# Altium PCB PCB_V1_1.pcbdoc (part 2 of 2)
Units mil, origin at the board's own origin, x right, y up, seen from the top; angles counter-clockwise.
Board outline 2047.24 x 3937.01 mil, 2 copper layers (Top Layer, Bottom Layer), stack 62.206 mil thick; 99 components, 62 nets, 329 pads, 46 vias.
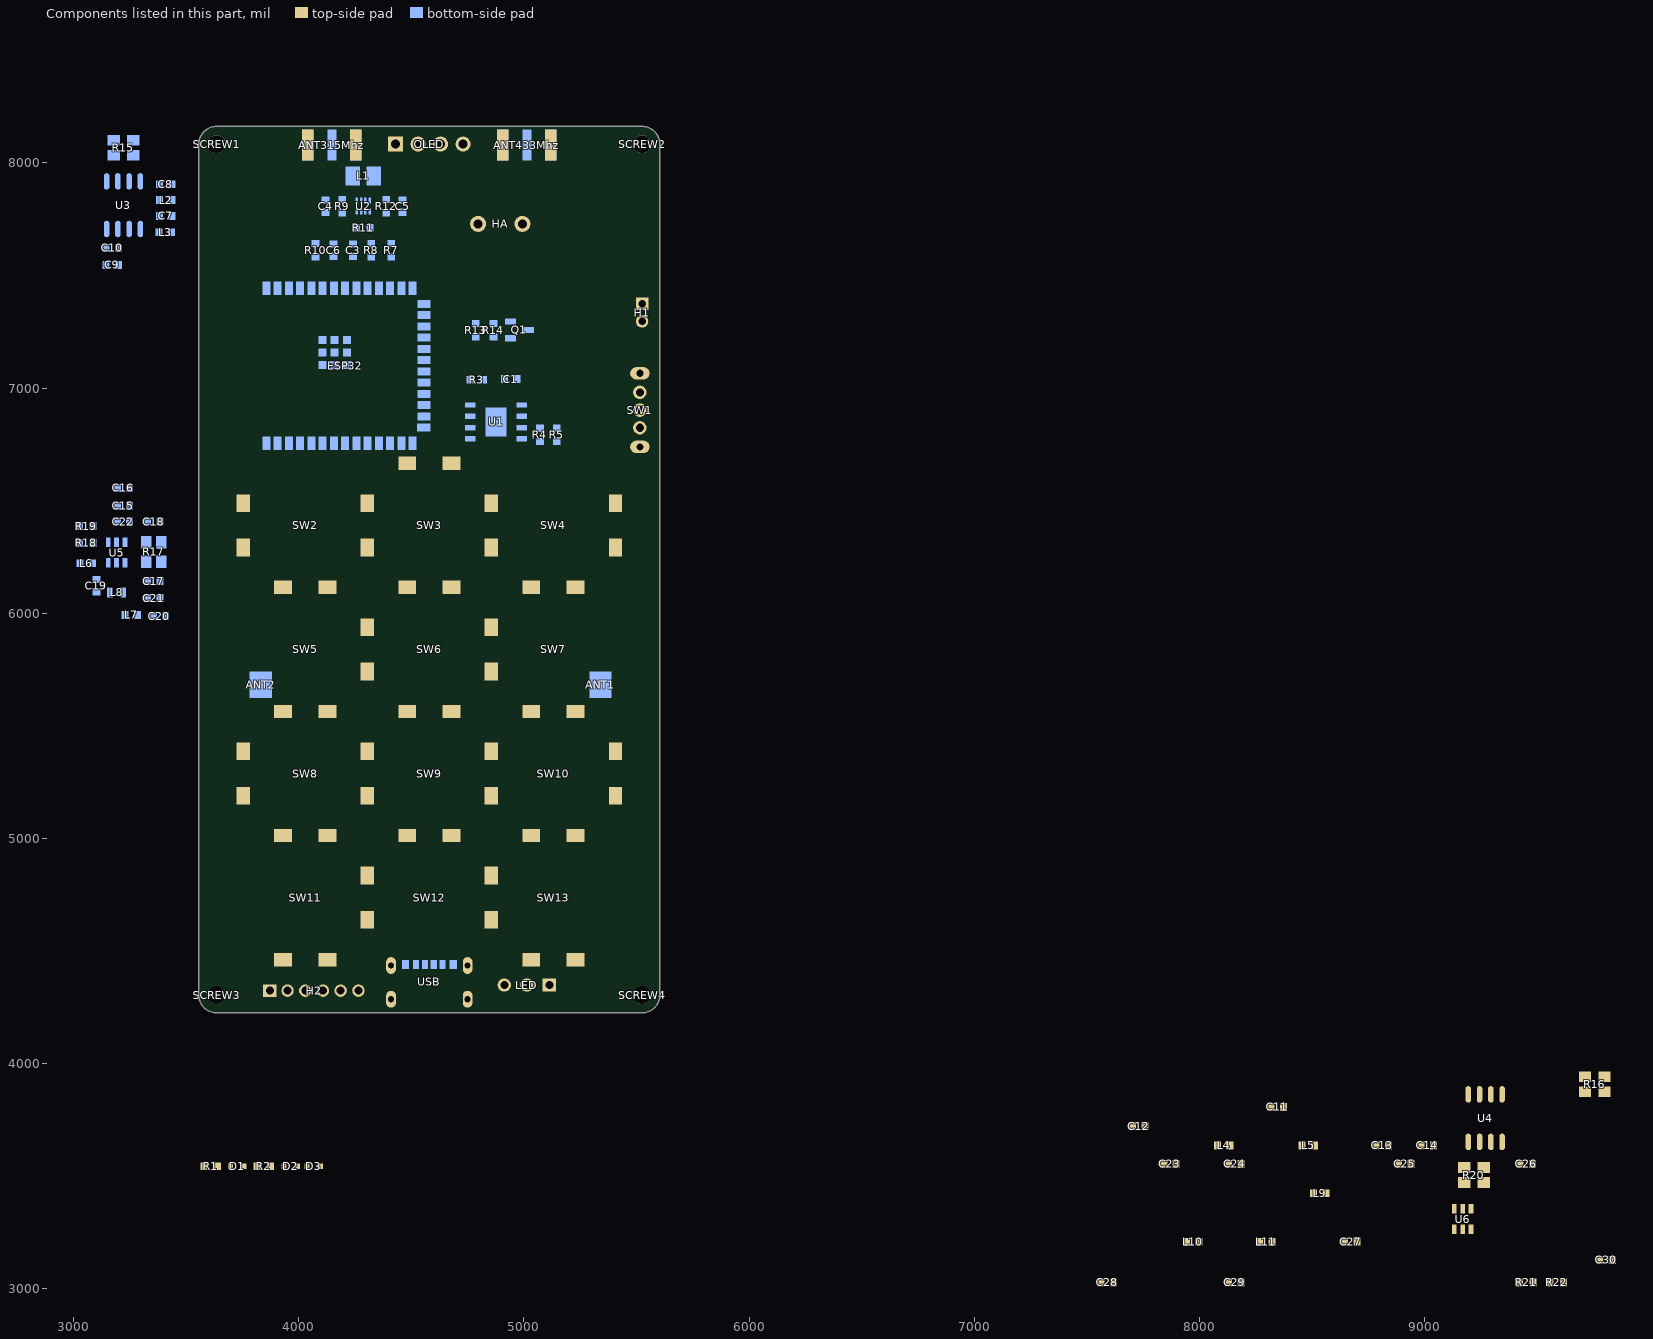
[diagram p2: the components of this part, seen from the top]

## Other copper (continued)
Bottom Layer:
  region net 433ANT: 5046.21,7999 5036.02,7971.29 ccw(c4966.71,7939.25) 4993.07,8010.91 5032.44,8010.91 ccw(c5055.12,8023.21)
  region net 315ANT: 4160.83,7987.48 4131.3,7987.48 ccw(c4066.33,7987.48) 4126.93,8010.91 4166.3,8010.91 ccw(c4213.7,7987.48)
  region net B+: 5475.25,6989.16 5478.71,7013.98 5479.83,7012.97 5481.09,7012.06 5483.96,7010.5 5487.16,7009.31 5490.59,7008.51 5494.09,7008.11 5497.55,7008.11 5500.83,7008.53 5503.81,7009.38 5487.94,6967.57 5484.97,6973.81 5482.56,6979.07 5481.23,6981.53 5479.66,6983.98 5477.71,6986.49
  region net VCC: 5478.51,6924.56 5492.65,6938.7 5495.17,6936.58 5497.8,6935.05 5500.55,6934.02 5503.43,6933.38 5506.44,6933.02 5509.57,6932.84 5516.24,6932.59 5484.62,6900.97 5484.37,6907.64 5484.19,6910.77 5483.83,6913.78 5483.19,6916.65 5482.16,6919.41 5480.63,6922.04
  region net VBUS: 4648.74,4410.85 4628.74,4410.85 ccw(c4613.62,4410.85) 4624.96,4420.85 4652.52,4420.85 ccw(c4663.86,4410.85)
  region net VBUS: 4628.74,4464.8 4648.74,4464.8 ccw(c4653.42,4464.8) 4652.52,4460.22 4624.96,4460.22 ccw(c4624.07,4464.8)
  region net VBUS: 4631.07,4477.48 4651.07,4477.48 ccw(c4754.09,4477.48) 4652.52,4460.22 4624.96,4460.22 ccw(c4603.6,4477.48)
  region net VBUS: 4510.63,4470.22 4530.63,4470.22 ccw(c4545.75,4470.22) 4534.41,4460.22 4506.85,4460.22 ccw(c4495.52,4470.22)
  region net TXD: 4152.28,4343.46 4166.43,4357.6 4168.61,4355.75 4170.97,4354.34 4173.48,4353.3 4176.11,4352.58 4178.85,4352.09 4181.68,4351.78 4187.52,4351.41 4158.47,4322.36 4158.11,4328.2 4157.79,4331.03 4157.31,4333.78 4156.58,4336.41 4155.55,4338.92 4154.14,4341.27
  region net BOOT: 3983.47,4304.34 3969.33,4290.19 3967.14,4292.05 3964.78,4293.46 3962.28,4294.49 3959.65,4295.22 3956.9,4295.71 3954.07,4296.02 3948.23,4296.38 3977.28,4325.43 3977.65,4319.59 3977.96,4316.76 3978.45,4314.02 3979.17,4311.39 3980.21,4308.88 3981.62,4306.52
  region net $1N804: 4717.1,6834.58 4732.79,6847.18 ccw(c4764.61,6889.61) 4764.61,6836.57 4737.9,6812.95 ccw(c4178.52,6296)
  region net VBUS: 4796.07,6932.48 4796.07,6912.48 ccw(c4785.14,6786.03) 4785.14,6912.95 4785.14,6936.57 ccw(c4796.07,6949.1)
  region net B+: 5021.07,6937.48 5021.07,6917.48 ccw(c5021.07,6909.92) 5014.14,6912.95 5014.14,6936.57 ccw(c5014.14,6963.45)
  region net $1N7064: 5044.14,6884.76 5044.14,6864.76 ccw(c5044.14,6615.37) 5014.14,6862.95 5014.14,6886.57 ccw(c5044.14,7134.15)
  region net $1N6847: 5044.14,6834.76 5044.14,6814.76 ccw(c5044.14,6565.37) 5014.14,6812.95 5014.14,6836.57 ccw(c5044.14,7084.15)
  region net VBUS: 4962.87,6764.76 4962.87,6784.76 ccw(c4962.87,6790.16) 4966.9,6786.57 4966.9,6762.95 ccw(c4962.87,6759.37)
  region net VBUS: 5001.07,6732.95 4981.07,6732.95 ccw(c4942.22,6732.95) 4966.9,6762.95 5014.14,6762.95 ccw(c5042.02,6732.95)
  region net +3.3V: 3895.48,7503.51 3915.48,7503.51 ccw(c3977.65,7503.51) 3923.19,7473.51 3887.76,7473.51 ccw(c3833.3,7503.51)
  region net EN: 3945.48,7476.89 3965.48,7476.89 ccw(c3973.19,7483.99) 3973.19,7473.51 3937.76,7473.51 ccw(c3937.76,7483.99)
  region net ADC: 3995.64,7486.89 4015.32,7486.89 ccw(c4030.64,7486.89) 4023.19,7473.51 3987.76,7473.51 ccw(c3980.32,7486.89)
  region net 315_TX: 4215.48,7404.45 4195.48,7404.45 ccw(c4185.14,7404.45) 4187.76,7414.45 4223.19,7414.45 ccw(c4225.82,7404.45)
  region net 433_TX: 4245.48,7482.48 4265.48,7482.48 ccw(c4274.56,7482.48) 4273.19,7473.51 4237.76,7473.51 ccw(c4236.4,7482.48)
  region net I2C_SDA: 4615.4,7384.49 4615.4,7364.49 ccw(c4615.4,7302.31) 4585.4,7356.77 4585.4,7392.2 ccw(c4615.4,7446.66)
  region net BUZZER: 4615.4,7334.49 4615.4,7314.49 ccw(c4615.4,7252.31) 4585.4,7306.77 4585.4,7342.2 ccw(c4615.4,7396.66)
  region net 433_RX: 4615.4,7134.49 4615.4,7114.49 ccw(c4615.4,7052.31) 4585.4,7106.77 4585.4,7142.2 ccw(c4615.4,7196.66)
  region net KEY_ENTER: 4615.4,7084.49 4615.4,7064.49 ccw(c4615.4,7002.31) 4585.4,7056.77 4585.4,7092.2 ccw(c4615.4,7146.66)
  region net KEY_3: 4614.06,7034.49 4614.06,7014.49 ccw(c4614.06,6957.39) 4585.4,7006.77 4585.4,7042.2 ccw(c4614.06,7091.58)
  region net KEY_6: 4604.06,6984.49 4604.06,6964.49 ccw(c4604.06,6938.06) 4585.4,6956.77 4585.4,6992.2 ccw(c4604.06,7010.92)
  region net KEY_9: 4591.07,6934.49 4591.07,6914.49 ccw(c4593.48,6906.77) 4585.4,6906.77 4585.4,6942.2 ccw(c4593.48,6942.2)
  region net KEY_MENU: 4508.14,6840.41 4507.78,6868.34 ccw(c4421.68,6954.43) 4526.34,6892.2 4526.34,6856.77 ccw(c4670.91,6677.64)
  region net KEY_2: 4564.69,6776.77 4544.69,6776.77 ccw(c4507.19,6776.77) 4529.69,6806.77 4579.69,6806.77 ccw(c4602.19,6776.77)
  region net BOOT: 4515.48,6695.47 4495.48,6695.47 ccw(c4433.3,6695.47) 4487.76,6725.47 4523.19,6725.47 ccw(c4577.65,6695.47)
  region net KEY_5: 4465.48,6695.47 4445.48,6695.47 ccw(c4383.3,6695.47) 4437.76,6725.47 4473.19,6725.47 ccw(c4527.65,6695.47)
  region net KEY_8: 4416.07,6695.47 4396.07,6695.47 ccw(c4337.73,6695.47) 4387.76,6725.47 4423.19,6725.47 ccw(c4482.76,6695.47)
  region net KEY_BACK: 4366.07,6695.47 4346.07,6695.47 ccw(c4287.73,6695.47) 4337.76,6725.47 4373.19,6725.47 ccw(c4432.76,6695.47)
  region net KEY_1: 4315.48,6695.47 4295.48,6695.47 ccw(c4233.3,6695.47) 4287.76,6725.47 4323.19,6725.47 ccw(c4377.65,6695.47)
  region net KEY_4: 4265.48,6695.47 4245.48,6695.47 ccw(c4183.3,6695.47) 4237.76,6725.47 4273.19,6725.47 ccw(c4327.65,6695.47)
  region net KEY_7: 4215.48,6695.47 4195.48,6695.47 ccw(c4133.3,6695.47) 4187.76,6725.47 4223.19,6725.47 ccw(c4277.65,6695.47)
  region net 315_RX: 4115.48,6695.47 4095.48,6695.47 ccw(c4033.3,6695.47) 4087.76,6725.47 4123.19,6725.47 ccw(c4177.65,6695.47)
  region net RXD: 4065.48,6695.47 4045.48,6695.47 ccw(c3983.3,6695.47) 4037.76,6725.47 4073.19,6725.47 ccw(c4127.65,6695.47)
  region net TXD: 4015.48,6695.47 3995.48,6695.47 ccw(c3933.3,6695.47) 3987.76,6725.47 4023.19,6725.47 ccw(c4077.65,6695.47)
  region net I2C_SCL: 3945.48,6792.48 3965.48,6792.48 ccw(c3973.44,6792.48) 3973.19,6784.53 3937.76,6784.53 ccw(c3937.52,6792.48)
  region net $1N6847: 5024.06,6814.76 5024.06,6834.76 ccw(c5024.06,6974.7) 5054.06,6838.02 5054.06,6806.27 ccw(c5024.06,6757.56)
  region net $1N11631: 5081.07,6716.95 5061.07,6716.95 ccw(c4993.35,6716.95) 5054.06,6746.95 5088.07,6746.95 ccw(c5148.78,6716.95)
  region net $1N7064: 5136.07,6852.48 5156.07,6852.48 ccw(c5174.5,6852.48) 5163.07,6838.02 5129.06,6838.02 ccw(c5117.64,6852.48)
  region net $1N7056: 5156.07,6716.95 5136.07,6716.95 ccw(c5068.35,6716.95) 5129.06,6746.95 5163.07,6746.95 ccw(c5223.78,6716.95)
  region net $1N804: 4741.07,7027.48 4741.07,7047.48 ccw(c4737.8,7054.49) 4745.53,7054.49 4745.53,7020.47 ccw(c4737.8,7020.47)
  region net +3.3V: 4568.39,8054.3 4550.62,8043.79 4549.09,8045.2 4547.6,8046.37 4546.12,8047.33 4544.66,8048.08 4541.73,8049.11 4538.73,8049.64 4535.57,8049.87 4532.19,8049.99 4528.48,8050.2 4524.39,8050.69 4563.11,8082.15 4562.65,8074.32 4562.55,8070.61 4562.7,8067.04 4563.24,8063.62 4563.69,8061.96 4564.28,8060.35 4565.03,8058.77 4565.96,8057.24 4567.07,8055.75
  region net $1N7056: 5138.75,4389.03 5152.89,4374.89 ccw(c5195.32,4343.07) 5142.29,4343.07 5106.93,4378.43 ccw(c5106.93,4431.46)
  region net VBUS: 5022.76,4314.17 5002.76,4314.17 5002.69,4315.75 5002.49,4317.13 5002.17,4318.33 5001.73,4319.38 5000.54,4321.12 4999.01,4322.55 4995.16,4325.3 4992.99,4327.01 4990.75,4329.21 5034.77,4329.21 5032.53,4327.01 5030.36,4325.3 5026.51,4322.55 5024.98,4321.12 5023.79,4319.38 5023.35,4318.33 5023.03,4317.13 5022.83,4315.75
  region net $1N11631: 4934.22,4384.5 4948.37,4370.36 4946.29,4367.91 4944.79,4365.33 4943.76,4362.62 4943.1,4359.79 4942.72,4356.84 4942.51,4353.76 4942.24,4347.25 4911.12,4378.38 4917.63,4378.65 4920.7,4378.86 4923.65,4379.24 4926.48,4379.9 4929.19,4380.93 4931.77,4382.43
  region net $1N15783: 4886.03,7211.46 4886.03,7231.46 ccw(c4886.03,7352.41) 4916.03,7235.24 4916.03,7207.68 ccw(c4886.03,7090.51)
  region net $1N15750: 5009.38,7302.64 5029.38,7302.64 ccw(c5067.49,7302.64) 5043.98,7272.64 4994.77,7272.64 ccw(c4971.26,7302.64)
  region net +3.3V: 5041.5,7739.41 5041.5,7719.41 5039.29,7719.32 5037.28,7719.04 5035.43,7718.6 5033.72,7718 5032.14,7717.26 5030.66,7716.38 5027.92,7714.28 5025.33,7711.8 5022.71,7709.03 5019.89,7706.06 5016.7,7703 5016.7,7755.82 5019.89,7752.76 5022.71,7749.79 5025.33,7747.02 5027.92,7744.54 5030.66,7742.44 5032.14,7741.56 5033.72,7740.82 5035.43,7740.22 5037.28,7739.78 5039.29,7739.5
  region net +3.3V: 4951.76,7756.58 4965.9,7770.72 4967.53,7769.23 4969.15,7768 4970.77,7767 4972.4,7766.22 4974.04,7765.63 4975.71,7765.2 4979.13,7764.75 4982.72,7764.67 4986.53,7764.78 4990.62,7764.88 4995.05,7764.79 4957.7,7727.44 4957.6,7731.86 4957.7,7735.95 4957.81,7739.76 4957.74,7743.35 4957.28,7746.78 4956.86,7748.44 4956.26,7750.08 4955.48,7751.71 4954.49,7753.33 4953.26,7754.95
  region net B+: 5505.01,7262.64 5490.87,7276.78 5492.72,7278.97 5494.13,7281.32 5495.17,7283.83 5495.89,7286.46 5496.38,7289.2 5496.69,7292.03 5497.05,7297.87 5526.1,7268.82 5520.26,7268.46 5517.43,7268.15 5514.69,7267.66 5512.06,7266.93 5509.55,7265.9 5507.2,7264.49
  region net B+: 5486.91,7286.5 5486.91,7306.18 5489.79,7306.42 5492.47,7307.1 5494.96,7308.16 5497.32,7309.52 5499.58,7311.14 5501.79,7312.95 5506.2,7316.88 5506.2,7275.8 5501.79,7279.73 5499.58,7281.53 5497.32,7283.15 5494.96,7284.52 5492.47,7285.58 5489.79,7286.26
  region net 433ANT: 5427.9,5696.93 5427.9,5667.4 ccw(c5427.9,5621.72) 5388.74,5645.26 5388.74,5719.08 ccw(c5427.9,5742.61)
  region net 315ANT: 3739.63,5685.66 3739.63,5718.04 ccw(c3756.05,5751.7) 3781.85,5724.56 3781.85,5650.75 ccw(c3703.65,5599.15)
  region net B+: 5015.23,7049.76 5015.23,7029.76 ccw(c5015.23,6967.59) 4985.23,7022.05 4985.23,7057.48 ccw(c5015.23,7111.94)
  region net ADC: 4250.91,7547.48 4231.22,7547.48 ccw(c4197.41,7547.48) 4223.35,7569.17 4258.78,7569.17 ccw(c4284.73,7547.48)
  region net ADC: 4288.31,7592.66 4288.31,7572.98 ccw(c4288.31,7456.52) 4258.78,7569.17 4258.78,7600.67 ccw(c4288.31,7651.12)
  region net EN: 4106.68,7570.54 4106.68,7590.54 ccw(c4106.68,7640.05) 4136.68,7600.67 4136.68,7569.17 ccw(c4106.68,7241.39)
  region net VCC: 4458.07,7652.14 4458.07,7632.14 ccw(c4458.07,7552.61) 4428.07,7626.27 4428.07,7658.02 ccw(c4458.07,7731.67)
  region net ADC: 4364.53,7572.98 4364.53,7592.66 ccw(c4364.53,7667.94) 4394.06,7598.7 4394.06,7566.95 ccw(c4364.53,7497.7)
  region net ADC: 4274.53,7572.98 4274.53,7592.66 ccw(c4274.53,7667.94) 4304.06,7598.7 4304.06,7566.95 ccw(c4274.53,7497.7)
  region net ADC: 4367.6,7592.66 4367.6,7572.98 ccw(c4367.6,7497.7) 4338.07,7566.95 4338.07,7598.7 ccw(c4367.6,7667.94)
  region net $1N15783: 4832.1,7231.46 4832.1,7211.46 ccw(c4832.1,-9960.11) 4802.1,7211.43 4802.1,7243.18 ccw(c4832.1,7275.7)
  region net BUZZER: 4757.02,7302.11 4772.29,7315.12 ccw(c4802.77,7345.6) 4802.1,7302.5 4768.08,7270.75 ccw(c4718.12,7270.75)
  region net $1N15783: 4911.38,7231.46 4911.38,7211.46 ccw(c4911.38,-9960.11) 4881.38,7211.43 4881.38,7243.18 ccw(c4911.38,7275.7)
  region net $1N15783: 4817.37,7211.46 4817.37,7231.46 ccw(c4817.37,7275.7) 4847.37,7243.18 4847.37,7211.43 ccw(c4817.37,-9960.11)
  region net EN: 4049.01,7556.51 4039.5,7574.83 ccw(c3965.01,7649.32) 4057.39,7598.7 4080.33,7566.95 ccw(c4080.33,7514.75)
  region net EN: 4121.41,7590.54 4121.41,7570.54 ccw(c4121.41,7443.66) 4091.41,7566.95 4091.41,7598.7 ccw(c4121.41,7649.81)
  region net +3.3V: 4044.29,7654.92 4058.59,7668.46 ccw(c4089.91,7710.21) 4089.91,7658.02 4057.39,7626.27 ccw(c4012.37,7623)
  region net $1N15750: 5029.38,7336.38 5009.38,7336.38 5009.02,7345.29 5008.92,7350.06 5009.18,7354.17 5032.96,7350.79 5032.54,7348.62 5032.02,7346.78 5030.83,7343.61 5030.27,7342.07 5029.81,7340.43 5029.49,7338.57
  region net I2C_SDA: 4727.95,7455.22 4713.81,7469.36 4715.62,7471.3 4717.23,7473.23 4719.84,7476.81 4721.62,7479.58 4722.58,7480.97 4739.56,7463.99 4738.16,7463.04 4735.4,7461.25 4731.81,7458.64 4729.88,7457.03
  region net I2C_SCL: 4501.07,7363.07 4481.07,7363.07 4480.98,7365.72 4480.75,7368.22 4480.06,7372.6 4479.37,7375.82 4479.06,7377.48 4503.07,7377.48 4502.76,7375.82 4502.07,7372.6 4501.38,7368.22 4501.15,7365.72
  region net EN: 3972.95,7480.22 3958.81,7494.36 3960.62,7496.3 3962.23,7498.23 3964.84,7501.81 3966.62,7504.58 3967.58,7505.97 3984.56,7488.99 3983.16,7488.04 3980.4,7486.25 3976.81,7483.64 3974.88,7482.03
  region net EN: 3979.3,7514.63 3993.22,7500.71 3991.41,7498.77 3989.81,7496.83 3987.24,7493.2 3985.49,7490.4 3984.56,7488.99 3967.58,7505.97 3968.99,7506.91 3971.79,7508.66 3975.42,7511.23 3977.36,7512.82
  region net +3.3V: 5476.66,6207.48 5476.66,6227.48 5479.3,6227.57 5481.81,6227.79 5486.19,6228.48 5489.41,6229.17 5491.07,6229.49 5491.07,6205.47 5489.41,6205.79 5486.19,6206.48 5481.81,6207.17 5479.3,6207.39
  region net TXD: 3995.48,6706.89 4015.48,6706.89 4015.56,6704.24 4015.79,6701.74 4016.48,6697.36 4017.17,6694.14 4017.49,6692.48 3993.47,6692.48 3993.78,6694.14 3994.47,6697.36 3995.16,6701.74 3995.39,6704.24
  region net TXD: 3693.33,4454.36 3679.18,4440.22 3677.25,4442.03 3675.32,4443.64 3671.74,4446.25 3668.97,4448.04 3667.58,4448.99 3684.56,4465.97 3685.51,4464.58 3687.3,4461.81 3689.91,4458.23 3691.52,4456.3
  region net RXD: 4045.48,6706.89 4065.48,6706.89 4065.56,6704.24 4065.79,6701.74 4066.48,6697.36 4067.17,6694.14 4067.49,6692.48 4043.47,6692.48 4043.78,6694.14 4044.47,6697.36 4045.16,6701.74 4045.39,6704.24
  region net 433_TX: 5106.66,7492.48 5106.66,7512.48 5109.3,7512.57 5111.81,7512.79 5116.19,7513.48 5119.41,7514.17 5121.07,7514.49 5121.07,7490.47 5119.41,7490.79 5116.19,7491.48 5111.81,7492.17 5109.3,7492.39
  region net 433_TX: 5216.64,7922.48 5216.64,7902.48 5214,7902.39 5211.49,7902.17 5207.11,7901.48 5203.89,7900.79 5202.23,7900.47 5202.23,7924.49 5203.89,7924.17 5207.11,7923.48 5211.49,7922.79 5214,7922.57
  region net KEY_9: 4923.81,4930.6 4937.95,4944.74 4939.88,4942.93 4941.81,4941.32 4945.4,4938.71 4948.16,4936.92 4949.56,4935.97 4932.58,4918.99 4931.62,4920.39 4929.84,4923.15 4927.23,4926.73 4925.62,4928.67
  region net KEY_7: 4195.48,4936.89 4215.48,4937.48 4215.57,4935.06 4215.83,4933.17 4216.63,4930.27 4217.51,4927.38 4217.85,4925.49 4218.06,4923.07 4194.07,4921.89 4194.03,4924.39 4194.14,4926.35 4194.64,4929.39 4195.21,4932.43 4195.4,4934.39
  region net KEY_6: 4766.07,5481.89 4786.07,5481.89 4786.15,5479.24 4786.38,5476.74 4787.07,5472.36 4787.76,5469.14 4788.07,5467.48 4764.06,5467.48 4764.37,5469.14 4765.06,5472.36 4765.75,5476.74 4765.98,5479.24
  region net KEY_3: 4811.07,6080.89 4831.07,6086.35 4830.96,6084.94 4830.72,6083.64 4830.22,6081.39 4830.16,6080.42 4830.36,6079.52 4830.93,6078.7 4831.95,6077.95 4815.15,6072.48 4815.49,6073.79 4815.27,6074.85 4814.65,6075.73 4813.78,6076.54 4812.83,6077.36 4811.96,6078.3 4811.32,6079.44
  region net KEY_2: 4571.07,6066.89 4591.07,6066.89 4591.15,6064.24 4591.38,6061.74 4592.07,6057.36 4592.76,6054.14 4593.07,6052.48 4569.06,6052.48 4569.37,6054.14 4570.06,6057.36 4570.75,6061.74 4570.98,6064.24
  region net KEY_1: 4295.48,6187.48 4315.48,6187.48 4315.57,6185.06 4315.83,6183.17 4316.63,6180.27 4317.51,6177.38 4317.85,6175.49 4318.06,6173.07 4294.07,6171.89 4294.02,6174.48 4294.13,6176.52 4294.63,6179.68 4295.2,6182.84 4295.4,6184.88
  region net KEY_ENTER: 4846.07,6571.89 4866.07,6571.89 4866.15,6569.24 4866.38,6566.74 4867.07,6562.36 4867.76,6559.14 4868.07,6557.48 4844.06,6557.48 4844.37,6559.14 4845.06,6562.36 4845.75,6566.74 4845.98,6569.24
  region net KEY_MENU: 4504.19,6864.74 4518.33,6850.6 4516.52,6848.67 4514.91,6846.73 4512.3,6843.15 4510.51,6840.39 4509.56,6838.99 4492.58,6855.97 4493.97,6856.92 4496.74,6858.71 4500.32,6861.32 4502.25,6862.93
  region net KEY_5: 4445.48,5856.89 4465.48,5856.89 4465.56,5854.24 4465.79,5851.74 4466.48,5847.36 4467.17,5844.14 4467.49,5842.48 4443.47,5842.48 4443.78,5844.14 4444.47,5847.36 4445.16,5851.74 4445.39,5854.24
  region net KEY_8: 4396.07,4851.89 4416.07,4851.89 4416.15,4849.24 4416.38,4846.74 4417.07,4842.36 4417.76,4839.14 4418.07,4837.48 4394.06,4837.48 4394.37,4839.14 4395.06,4842.36 4395.75,4846.74 4395.98,4849.24
  region net KEY_BACK: 4346.07,6606.89 4366.07,6606.89 4366.15,6604.24 4366.38,6601.74 4367.07,6597.36 4367.76,6594.14 4368.07,6592.48 4344.06,6592.48 4344.37,6594.14 4345.06,6597.36 4345.75,6601.74 4345.98,6604.24
  region net KEY_4: 4245.48,5401.89 4265.48,5401.89 4265.56,5399.24 4265.79,5396.74 4266.48,5392.36 4267.17,5389.14 4267.49,5387.48 4243.47,5387.48 4243.78,5389.14 4244.47,5392.36 4245.16,5396.74 4245.39,5399.24
  region net B+: 5051.07,6966.97 5031.07,6966.97 5030.98,6969.62 5030.75,6972.12 5030.06,6976.5 5029.37,6979.72 5029.06,6981.38 5053.07,6981.38 5052.76,6979.72 5052.07,6976.5 5051.38,6972.12 5051.15,6969.62
  region net B+: 5031.07,6995.79 5051.07,6995.79 5051.15,6993.14 5051.38,6990.64 5052.07,6986.26 5052.76,6983.04 5053.07,6981.38 5029.06,6981.38 5029.37,6983.04 5030.06,6986.26 5030.75,6990.64 5030.98,6993.14
  region net +3.3V: 5361.07,7786.89 5381.07,7786.89 5381.15,7784.24 5381.38,7781.74 5382.07,7777.36 5382.76,7774.14 5383.07,7772.48 5359.06,7772.48 5359.37,7774.14 5360.06,7777.36 5360.75,7781.74 5360.98,7784.24
  region net VBUS: 4594,4495.41 cw(c4460.42,4361.83) 4631.07,4442.86 4641.07,4472.48
  region net +3.3V: 3966.07,7648.94 cw(c4066.07,7648.94) 3986.07,7708.94 3956.07,7718.78

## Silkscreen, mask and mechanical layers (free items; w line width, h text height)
Bottom Silkscreen Layer:
  drawing of 10 lines, arcs and shapes, not listed
  text "BAT 503048 / 800mAh" at 4934.02,5642.8 h120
